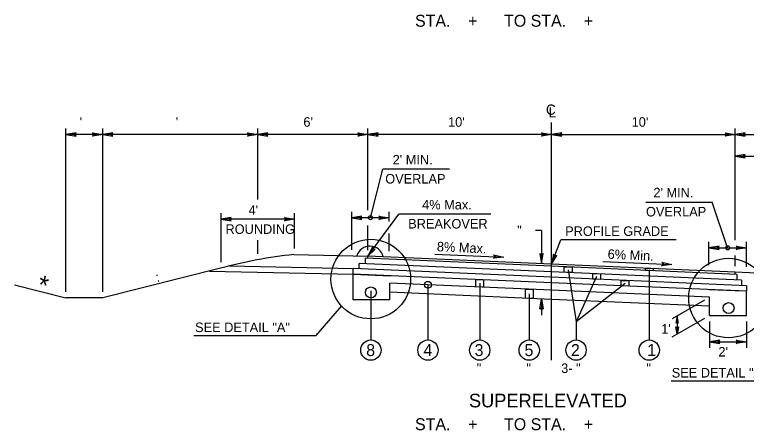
# Model space of a CAD drawing. Extents: x -540 to 1231, y -564 to 421.
# Drawn here: x 503.4 to 610.8, y 180.3 to 241.3 of the extents above; entities that cross this region are included whole.
import ezdxf

# ---------------------------------------------------------------- set-up
doc = ezdxf.new("R2010")
doc.units = 0
doc.layers.add('1', color=7, linetype='Continuous')
doc.layers.add('Des_ Drain_ Ftrs', color=7, linetype='Continuous')

msp = doc.modelspace()

# ---------------------------------------------------------------- linework, layer by layer
at = {"layer": '1'}
for p, q in [((510.92, 200.6), (510.92, 224.55)), ((516.31, 200.6), (516.31, 224.55)), ((539.07, 214.16), (539.07, 224.55)), ((555.23, 212.59), (555.23, 224.55)), ((582.17, 190.55), (582.17, 225.43)), ((609.12, 208.17), (609.12, 224.55)), ((516.31, 223.67), (510.92, 223.67)), ((539.07, 223.67), (516.31, 223.67)), ((555.23, 223.67), (539.07, 223.67)), ((582.17, 223.67), (555.23, 223.67)), ((582.17, 223.67), (609.12, 223.67)), ((609.12, 223.67), (625.28, 223.67)), ((609.12, 220.51), (631.48, 220.51)), ((555.6, 211.46), (557.44, 218.58)), ((567.2, 218.58), (557.44, 218.58)), ((596, 213.75), (605.76, 213.75)), ((608.01, 207.04), (605.76, 213.75)), ((533.68, 204.95), (533.68, 212.15)), ((544.46, 206.93), (544.46, 212.15)), ((552.86, 206.75), (552.86, 212.34)), ((555.23, 205.82), (559.77, 211.98)), ((558.34, 210.92), (558.34, 212.34)), ((573.25, 211.98), (559.77, 211.98)), ((544.46, 211.27), (533.68, 211.27)), ((558.34, 211.46), (552.86, 211.46)), ((555.23, 206.69), (555.23, 210.34)), ((580.72, 209.58), (579.84, 209.58)), ((580.72, 209.58), (580.72, 204.7)), ((558.34, 206.56), (558.34, 209.15)), ((539.07, 206.17), (539.07, 208.19)), ((582.18, 204.63), (583.56, 208.2)), ((600.48, 208.2), (583.56, 208.2)), ((605.27, 204.51), (605.27, 207.92)), ((610.76, 204.27), (610.76, 207.92)), ((605.27, 207.04), (610.76, 207.04)), ((544.36, 206.05), (555.23, 205.82)), ((582.17, 204.34), (554.89, 205.53)), ((554.89, 204.72), (554.89, 205.53)), ((582.17, 204.64), (555.23, 205.82)), ((555.23, 205.52), (555.23, 205.82)), ((565.03, 206.13), (575.15, 205.69)), ((609.12, 204.34), (609.12, 205.91)), ((533.59, 204.04), (516.31, 199.72)), ((534.91, 204.39), (553.04, 203.99)), ((582.17, 203.53), (553.96, 204.76)), ((553.96, 203.95), (553.96, 204.76)), ((609.12, 203.46), (582.17, 204.64)), ((609.35, 203.15), (582.17, 204.34)), ((589.71, 205.05), (599.82, 204.61)), ((531.99, 203.64), (553.04, 203.18)), ((582.17, 202.72), (553.04, 203.99)), ((553.04, 203.18), (553.04, 203.99)), ((582.17, 201.91), (553.04, 203.18)), ((553.04, 199.43), (553.04, 203.18)), ((553.04, 203.18), (555.23, 203.09)), ((555.23, 203.09), (558.53, 202.94)), ((610.06, 202.31), (582.17, 203.53)), ((584.61, 203.83), (585.77, 196.2)), ((596.51, 203.83), (596.51, 193.52)), ((620, 202.99), (609.12, 203.46)), ((609.12, 203.16), (609.12, 203.46)), ((609.35, 203.15), (609.35, 202.34)), ((582.17, 200.83), (558.43, 201.87)), ((558.43, 199.43), (558.43, 201.87)), ((610.76, 201.47), (582.17, 202.72)), ((610.76, 200.66), (582.17, 201.91)), ((588.78, 202.84), (585.77, 196.2)), ((610.06, 202.31), (610.06, 201.5)), ((503.39, 201.6), (510.92, 199.72)), ((564.04, 201.62), (564.04, 193.52)), ((571.63, 201.86), (571.63, 193.52)), ((605.37, 199.82), (582.17, 200.83)), ((592.96, 201.83), (585.77, 196.2)), ((609.12, 200.74), (605.28, 200.9)), ((610.76, 201.47), (610.76, 200.66)), ((516.31, 199.72), (510.92, 199.72)), ((555.66, 200.73), (555.66, 200.73)), ((555.66, 200.73), (555.66, 193.52)), ((582.17, 199.48), (558.43, 200.52)), ((578.9, 200.31), (578.9, 193.52)), ((605.37, 197.12), (605.37, 199.82)), ((605.37, 199.82), (605.37, 199.82)), ((610.76, 200.66), (609.11, 200.74)), ((610.76, 197.12), (610.76, 200.66)), ((558.43, 199.43), (553.04, 199.43)), ((580.72, 199.55), (580.72, 197.18)), ((605.37, 198.47), (582.17, 199.48)), ((604.61, 199.38), (599.85, 196.63)), ((547.62, 194.18), (551.36, 198.5)), ((604.61, 196.68), (599.84, 193.93)), ((600.62, 197.07), (600.6, 194.37)), ((605.37, 197.12), (610.76, 197.12)), ((585.77, 196.2), (585.77, 193.52)), ((605.37, 196.24), (605.37, 192.36)), ((610.76, 196.24), (610.76, 192.36)), ((529.69, 194.18), (547.62, 194.18)), ((605.37, 193.24), (610.76, 193.24)), ((599.71, 187.51), (618.49, 187.51))]:
    msp.add_line(p, q, dxfattribs=at)
for points in [[(584.03, 204.26), (585.18, 204.21), (585.18, 203.4), (584.03, 203.45)], [(595.94, 204.04), (597.09, 203.99), (597.09, 203.69), (595.94, 203.74)], [(588.21, 203.27), (589.35, 203.22), (589.35, 202.41), (588.21, 202.46)], [(571.06, 202.4), (572.21, 202.35), (572.21, 201.27), (571.06, 201.32)], [(592.38, 202.27), (593.53, 202.22), (593.53, 201.42), (592.38, 201.47)], [(578.33, 201), (579.48, 200.95), (579.48, 199.6), (578.33, 199.65)]]:
    msp.add_lwpolyline(points, close=True, dxfattribs=at)
for centre, radius in [((555.6, 211.46), 0.3), ((555.65, 202.46), 5.84), ((608.01, 207.04), 0.3), ((608.14, 199.68), 5.84), ((564.04, 201.62), 0.5), ((555.66, 200.5), 0.808), ((608.15, 198.2), 0.808), ((555.66, 192.03), 1.49), ((564.04, 192.03), 1.49), ((571.63, 192.03), 1.49), ((578.9, 192.03), 1.49), ((585.77, 192.03), 1.49), ((596.51, 192.03), 1.49)]:
    msp.add_circle(centre, radius, dxfattribs=at)
for centre, radius, start, end in [((555.51, 205.3), 2, 12.083, 163.9398), ((551.26, 139.22), 67.19, 95.8911, 105.2497)]:
    msp.add_arc(centre, radius, start, end, dxfattribs=at)
at = {"layer": 'Des_ Drain_ Ftrs'}
for points in [[(510.92, 223.67), (512.41, 223.42), (512.12, 223.67), (512.41, 223.92)], [(516.31, 223.67), (514.82, 223.42), (515.12, 223.67), (514.82, 223.92)], [(516.31, 223.67), (517.8, 223.42), (517.5, 223.67), (517.8, 223.92)], [(539.07, 223.67), (537.58, 223.42), (537.87, 223.67), (537.58, 223.92)], [(539.07, 223.67), (540.56, 223.42), (540.26, 223.67), (540.56, 223.92)], [(555.23, 223.67), (553.74, 223.42), (554.04, 223.67), (553.74, 223.92)], [(555.23, 223.67), (556.72, 223.42), (556.43, 223.67), (556.72, 223.92)], [(582.17, 223.67), (580.69, 223.42), (580.98, 223.67), (580.69, 223.92)], [(582.17, 223.67), (583.66, 223.42), (583.37, 223.67), (583.66, 223.92)], [(609.12, 223.67), (607.63, 223.42), (607.92, 223.67), (607.63, 223.92)], [(609.12, 223.67), (610.6, 223.42), (610.31, 223.67), (610.6, 223.92)], [(609.12, 220.51), (610.6, 220.26), (610.31, 220.51), (610.6, 220.76)], [(552.86, 211.46), (554.35, 211.22), (554.05, 211.46), (554.35, 211.71)], [(558.34, 211.46), (556.85, 211.22), (557.15, 211.46), (556.85, 211.71)], [(533.68, 211.27), (535.17, 211.02), (534.87, 211.27), (535.17, 211.52)], [(544.46, 211.27), (542.97, 211.02), (543.26, 211.27), (542.97, 211.52)], [(605.27, 207.04), (606.76, 206.79), (606.46, 207.04), (606.76, 207.29)], [(610.76, 207.04), (609.27, 206.79), (609.56, 207.04), (609.27, 207.29)], [(555.23, 205.82), (556.31, 206.87), (555.93, 206.78), (555.91, 207.16)], [(580.72, 204.7), (580.96, 206.19), (580.72, 205.9), (580.47, 206.19)], [(575.15, 205.69), (573.65, 205.51), (573.95, 205.74), (573.67, 206)], [(582.18, 204.63), (582.95, 205.93), (582.61, 205.75), (582.48, 206.11)], [(599.82, 204.61), (598.33, 204.42), (598.63, 204.66), (598.35, 204.92)], [(580.72, 199.55), (580.96, 198.06), (580.72, 198.36), (580.47, 198.06)], [(600.62, 197.07), (600.43, 195.99), (600.61, 196.2), (600.79, 195.99)], [(600.6, 194.37), (600.42, 195.45), (600.6, 195.24), (600.78, 195.45)], [(605.37, 193.24), (606.86, 192.99), (606.57, 193.24), (606.86, 193.49)], [(610.76, 193.24), (609.27, 192.99), (609.57, 193.24), (609.27, 193.49)]]:
    msp.add_lwpolyline(points, close=True, dxfattribs=at)

# ---------------------------------------------------------------- texts
at = {"layer": '1'}
for s, height, p in [('STA.    +      TO STA.    +     ', 1.75, (562.14, 239.5)), (" '", 1.4, (512.42, 224.82)), ("  '", 1.4, (525.99, 224.82)), ("6'", 1.4, (545.76, 224.82)), ("10'", 1.4, (566.99, 224.82)), ("10'", 1.4, (593.93, 224.82)), ("2' MIN.", 1.4, (558.86, 219.28)), ('OVERLAP', 1.4, (557.77, 216.48)), ("2' MIN.", 1.4, (597.12, 214.45)), ('4% Max.', 1.4, (563.19, 212.68)), ("4'", 1.4, (537.72, 211.89)), ('OVERLAP', 1.4, (596.03, 211.65)), ('ROUNDING', 1.4, (534.33, 209.09)), ('BREAKOVER', 1.4, (561.14, 209.88)), ('PROFILE GRADE', 1.4, (584.17, 208.79)), ('SEE DETAIL "A"', 1.4, (529.87, 194.68)), ('8', 1.75, (554.98, 191.16)), ('4', 1.75, (563.37, 191.16)), ('3', 1.75, (570.88, 191.16)), ('5', 1.75, (578.21, 191.16)), ('2', 1.75, (585.02, 191.16)), ('1', 1.75, (596.21, 191.16)), ("2'", 1.4, (606.66, 191.09)), (' "', 1.4, (570.69, 188.67)), (' "', 1.4, (577.96, 188.67)), ('3- "', 1.4, (583.59, 188.67)), (' "', 1.4, (595.57, 188.67)), ('SEE DETAIL "A"', 1.4, (599.81, 188.01)), ('SUPERELEVATED', 2, (570.05, 183.63)), ('STA.    +      TO STA.    +     ', 1.75, (562.14, 180.28))]:
    msp.add_text(s, height=height, dxfattribs=at).set_placement(p)
for s, height, rotation, p in [('  "', 1.4, 0.1438, (576.1, 208.88)), ('8% Max.', 1.4, 357.3765, (565.32, 206.55)), ('6% Min.', 1.4, 357.3727, (590.38, 205.45)), ('*', 2.8, 347.1521, (506.55, 200.37)), (' : ', 1.4, 14.2282, (523.77, 201.87)), ("1'", 1.4, 0.1438, (598.27, 194.46))]:
    msp.add_text(s, height=height, rotation=rotation, dxfattribs=at).set_placement(p)
at = {"layer": 'Des_ Drain_ Ftrs'}
for s, p in [('C', (581.35, 226.58)), ('L', (581.74, 226.19))]:
    msp.add_text(s, height=1.5, dxfattribs=at).set_placement(p)

doc.saveas('drawing.dxf')
